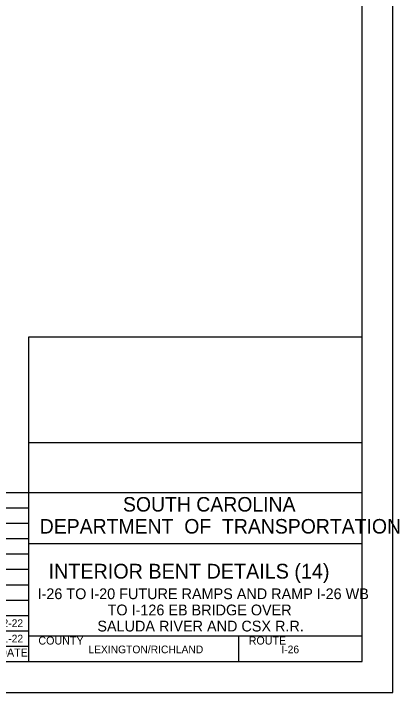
# Model space of a CAD drawing. Extents: x -133.1 to -97, y -1.7 to 20.3.
# Drawn here: x -103.3 to -97.03, y -1.69 to 9.34 of the extents above; entities that cross this region are included whole.
import ezdxf

# ---------------------------------------------------------------- set-up
doc = ezdxf.new("R2010")
doc.units = 0
for name, color, linetype in [('BR_BORDER LINES', 7, 'Continuous'), ('BR_TEXT', 7, 'Continuous'), ('Level 31', 7, 'Continuous')]:
    doc.layers.add(name, color=color, linetype=linetype)

msp = doc.modelspace()

# ---------------------------------------------------------------- linework, layer by layer
at = {"layer": 'BR_BORDER LINES'}
for p, q in [((-97.642, -1.191), (-97.642, 19.809)), ((-103.058, -1.191), (-103.058, 4.086)), ((-103.058, 4.086), (-97.642, 4.086)), ((-103.058, 2.371), (-97.642, 2.371)), ((-105.142, 1.559), (-97.642, 1.559)), ((-104.559, 1.309), (-103.058, 1.309)), ((-105.142, 1.059), (-103.058, 1.059)), ((-104.559, 0.809), (-103.058, 0.809)), ((-103.058, 0.726), (-103.058, 0.726)), ((-103.058, 0.726), (-97.641, 0.726)), ((-105.142, 0.559), (-103.058, 0.559)), ((-104.559, 0.309), (-103.058, 0.309)), ((-105.142, 0.059), (-103.058, 0.059)), ((-105.142, -0.191), (-103.058, -0.191)), ((-105.142, -0.441), (-103.058, -0.441)), ((-105.142, -0.691), (-103.058, -0.691)), ((-103.058, -0.774), (-97.642, -0.774)), ((-102.961, -0.774), (-97.642, -0.774)), ((-99.642, -1.191), (-99.642, -0.774)), ((-105.142, -0.941), (-103.058, -0.941)), ((-131.308, -1.191), (-97.642, -1.191))]:
    msp.add_line(p, q, dxfattribs=at)
at = {"layer": 'Level 31'}
msp.add_line((-100.35, 0.285), (-100.35, 0.285), dxfattribs=at)
msp.add_lwpolyline([(-133.141, -1.691), (-97.141, -1.691), (-97.141, 20.309), (-133.141, 20.309)], close=True, dxfattribs=at)

# ---------------------------------------------------------------- texts
at = {"layer": 'BR_TEXT'}
for s, height, p in [('SOUTH CAROLINA', 0.23587, (-101.527, 1.247)), ('DEPARTMENT  OF  TRANSPORTATION', 0.23587, (-102.879, 0.89)), ('INTERIOR BENT DETAILS (14)', 0.24, (-102.736, 0.158)), ('I-26 TO I-20 FUTURE RAMPS AND RAMP I-26 WB', 0.175, (-102.915, -0.176)), ('TO I-126 EB BRIDGE OVER', 0.175, (-101.777, -0.439)), ('02-22', 0.125, (-103.577, -0.629)), ('SALUDA RIVER AND CSX R.R.', 0.175, (-101.943, -0.701)), ('01-22', 0.125, (-103.577, -0.879)), ('COUNTY', 0.13, (-102.901, -0.913)), ('ROUTE', 0.13, (-99.484, -0.913)), ('DATE', 0.13, (-103.537, -1.108)), ('LEXINGTON/RICHLAND', 0.12499, (-102.089, -1.055)), ('I-26', 0.125, (-98.953, -1.055))]:
    msp.add_text(s, height=height, dxfattribs=at).set_placement(p)

doc.saveas('drawing.dxf')
